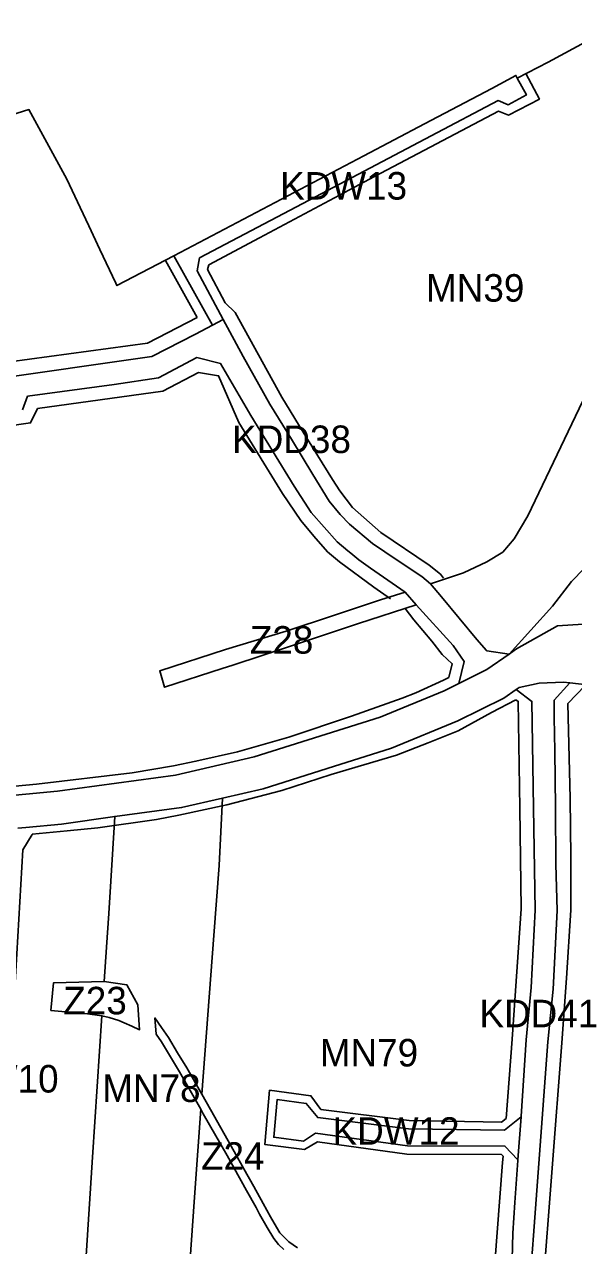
# Model space of a CAD drawing. Extents: x 7428841 to 7433518, y 5545054 to 5546840.
# Drawn here: x 7431956.4 to 7432155.6, y 5545406.8 to 5545850.4 of the extents above; entities that cross this region are included whole.
import ezdxf

# ---------------------------------------------------------------- set-up
doc = ezdxf.new("R2010")
doc.units = 0
for name, color, linetype in [('linie_rozgraniczajace', 7, 'Continuous'), ('linie_zabudowy_nieprzekraczalne', 7, 'Continuous'), ('oznaczenia_przeznaczen', 7, 'Continuous')]:
    doc.layers.add(name, color=color, linetype=linetype)

msp = doc.modelspace()

# ---------------------------------------------------------------- linework, layer by layer
at = {"layer": 'linie_rozgraniczajace'}
for points in [[(7432132.18, 5545621.69), (7432147.9, 5545639.12), (7432154.88, 5545648.03), (7432210.86, 5545705.54), (7432222.9, 5545721.64), (7432232.08, 5545736.14), (7432244.76, 5545759.7), (7432253.45, 5545777.62), (7432262.14, 5545795.55), (7432271.44, 5545817.17), (7432287.75, 5545858.73), (7432313.15, 5545921.27), (7432332.96, 5545968.95), (7432347.45, 5546006.55), (7432352.33, 5546020.89), (7432357.2, 5546035.24), (7432363.75, 5546056.3), (7432370.28, 5546073.1), (7432379.89, 5546097.52)], [(7432188.47, 5545859.56), (7432146.36, 5545836.73), (7432135.07, 5545830.88), (7432134.66, 5545831.89), (7432125.88, 5545827.16), (7432101.56, 5545814.32), (7432079.45, 5545802.66), (7432010.61, 5545766.29), (7431989.91, 5545755.55), (7431989.48, 5545756.43), (7431983.69, 5545768.63), (7431979.69, 5545777.2), (7431976.57, 5545783.86), (7431971.71, 5545794.23)], [(7432174.91, 5545747.04), (7432139.05, 5545671.94), (7432133.99, 5545663.57), (7432129.9, 5545658.64), (7432124.15, 5545655.2), (7432115.61, 5545651.14), (7432103.72, 5545647.14), (7432100.52, 5545649.81), (7432091.55, 5545655.81), (7432082.59, 5545661.8), (7432074.35, 5545668.92), (7432070.92, 5545672.36), (7432066.96, 5545677.25), (7432061.04, 5545686.93), (7432053.2, 5545699.7), (7432045.36, 5545712.47), (7432035.77, 5545729.82), (7432028.45, 5545743.22), (7432019.06, 5545760.95), (7432019.88, 5545765.56), (7432059.68, 5545786.57), (7432103.89, 5545809.9), (7432128.22, 5545822.74), (7432131.82, 5545821.25), (7432138.47, 5545824.77), (7432135.07, 5545830.88), (7432146.36, 5545836.73), (7432188.47, 5545859.56)], [(7432287.75, 5545858.73), (7432271.44, 5545817.17), (7432262.14, 5545795.55), (7432253.45, 5545777.62), (7432244.76, 5545759.7), (7432232.08, 5545736.14), (7432222.9, 5545721.64), (7432210.86, 5545705.54), (7432154.88, 5545648.03), (7432147.9, 5545639.12), (7432132.18, 5545621.69), (7432124.12, 5545622.82), (7432124.01, 5545622.95), (7432120.53, 5545626.94), (7432114.08, 5545634.7), (7432107.63, 5545642.46), (7432103.72, 5545647.14)], [(7432103.72, 5545647.14), (7432115.61, 5545651.14), (7432124.15, 5545655.2), (7432129.9, 5545658.64), (7432133.99, 5545663.57), (7432139.05, 5545671.94), (7432174.91, 5545747.04), (7432183.86, 5545765.9), (7432191.2, 5545780.73), (7432198.41, 5545796.09), (7432202.91, 5545805.04), (7432221.07, 5545842.2), (7432217.5, 5545843.79), (7432200.67, 5545852.98)], [(7432298.89, 5545854.26), (7432292.35, 5545837.77), (7432287.69, 5545826.02), (7432280.47, 5545808.59), (7432273.19, 5545791.34), (7432264.38, 5545773.09), (7432255.56, 5545754.84), (7432242.56, 5545730.56), (7432232.89, 5545715.25), (7432220.1, 5545698.07), (7432192.02, 5545669.12), (7432163.94, 5545640.18), (7432161, 5545636.55), (7432161.55, 5545631.78), (7432159.07, 5545632.52), (7432149.7, 5545631.91), (7432134.84, 5545623.57), (7432132.18, 5545621.69)], [(7431971.71, 5545794.23), (7431958.02, 5545819.48), (7431897.05, 5545800.35), (7431836.08, 5545781.23), (7431835.44, 5545785.08), (7431828.78, 5545823.75), (7431822.57, 5545843.63)], [(7431897.05, 5545800.35), (7431958.02, 5545819.48), (7431971.71, 5545794.23), (7431976.57, 5545783.86), (7431979.69, 5545777.2), (7431983.69, 5545768.63), (7431989.48, 5545756.43), (7431989.91, 5545755.55), (7432010.61, 5545766.29), (7432024.6, 5545741.15), (7432024.62, 5545741.12), (7432018.4, 5545737.92), (7432002.58, 5545729.76), (7431942.49, 5545721.23)], [(7431942.49, 5545721.23), (7432002.58, 5545729.76), (7432018.4, 5545737.92), (7432024.62, 5545741.12), (7432028.45, 5545743.22), (7432035.77, 5545729.82), (7432045.36, 5545712.47), (7432053.2, 5545699.7), (7432061.04, 5545686.93), (7432066.96, 5545677.25), (7432070.92, 5545672.36), (7432074.35, 5545668.92), (7432082.59, 5545661.8), (7432091.55, 5545655.81), (7432100.52, 5545649.81), (7432103.72, 5545647.14), (7432107.63, 5545642.46), (7432114.08, 5545634.7), (7432120.53, 5545626.94), (7432124.01, 5545622.95), (7432124.12, 5545622.82), (7432132.18, 5545621.69), (7432124.16, 5545616.01), (7432113.98, 5545610.97), (7432115.88, 5545618.94), (7432111.91, 5545624.76), (7432098.44, 5545639.51), (7432094.46, 5545644.16), (7432081.9, 5545652.94), (7432077.71, 5545655.86), (7432074.73, 5545658.29), (7432073.75, 5545659.16), (7432069.79, 5545662.45), (7432060.4, 5545673.09), (7432054.26, 5545682.68), (7432038.5, 5545708.36), (7432027.55, 5545727.17), (7432018.94, 5545729.39), (7432004.95, 5545721.98), (7431988.94, 5545719.56), (7431957.51, 5545715.35), (7431955.63, 5545710.38)], [(7431955.63, 5545710.38), (7431957.51, 5545715.35), (7431988.94, 5545719.56), (7432004.95, 5545721.98), (7432018.94, 5545729.39), (7432027.55, 5545727.17), (7432038.5, 5545708.36), (7432054.26, 5545682.68), (7432060.4, 5545673.09), (7432069.79, 5545662.45), (7432073.75, 5545659.16), (7432074.73, 5545658.29), (7432077.71, 5545655.86), (7432081.9, 5545652.94), (7432094.46, 5545644.16), (7432085.51, 5545641.36), (7432068.44, 5545635.66), (7432051.37, 5545629.96), (7432029.34, 5545623.36), (7432005.45, 5545615.58), (7432007.23, 5545609.6), (7432028.14, 5545616.39), (7432031.94, 5545617.63), (7432053.62, 5545624.84), (7432077.53, 5545632.81), (7432098.44, 5545639.51), (7432111.91, 5545624.76), (7432115.88, 5545618.94), (7432113.98, 5545610.97), (7432108.68, 5545608.34), (7432085.39, 5545598.8), (7432039.76, 5545584.32), (7432011.23, 5545577.7), (7431968.38, 5545571.86), (7431933.82, 5545568.58)], [(7431933.82, 5545568.58), (7431968.38, 5545571.86), (7432011.23, 5545577.7), (7432039.76, 5545584.32), (7432085.39, 5545598.8), (7432108.68, 5545608.34), (7432113.98, 5545610.97), (7432124.16, 5545616.01), (7432132.18, 5545621.69), (7432134.84, 5545623.57), (7432149.7, 5545631.91), (7432159.07, 5545632.52)], [(7432161.6, 5545610.32), (7432154.28, 5545611.17), (7432151.96, 5545611.44), (7432143.06, 5545611.08), (7432135.8, 5545609.55), (7432134.71, 5545608.78), (7432130.33, 5545605.68), (7432113.62, 5545597.4), (7432089.48, 5545587.51), (7432066.21, 5545580.13), (7432042.94, 5545572.74), (7432028.17, 5545569.31), (7432013.4, 5545565.89), (7431989.12, 5545562.68), (7431969.76, 5545559.94), (7431956.9, 5545558.72), (7431954.01, 5545558.44)], [(7432133.27, 5545401.81), (7432133.55, 5545411.29), (7432134.27, 5545422.46), (7432135.31, 5545437.71), (7432135.32, 5545437.91), (7432136.55, 5545453.6), (7432136.57, 5545453.8), (7432138.34, 5545481.5), (7432140.17, 5545500.5), (7432140.92, 5545514.58), (7432141.67, 5545528.66), (7432141.02, 5545565.76), (7432140.45, 5545604.48), (7432134.71, 5545608.78), (7432135.8, 5545609.55), (7432143.06, 5545611.08), (7432151.96, 5545611.44), (7432154.28, 5545611.17), (7432148.5, 5545604.9), (7432148.59, 5545598.65), (7432148.85, 5545586.48), (7432149.02, 5545565.9), (7432149.18, 5545545.32), (7432149.67, 5545528.57), (7432148.15, 5545499.91), (7432146.31, 5545480.82), (7432142.98, 5545436.66), (7432138.74, 5545379.48)], [(7432138.74, 5545379.48), (7432142.98, 5545436.66), (7432146.31, 5545480.82), (7432148.15, 5545499.91), (7432149.67, 5545528.57), (7432149.18, 5545545.32), (7432149.02, 5545565.9), (7432148.85, 5545586.48), (7432148.59, 5545598.65), (7432148.5, 5545604.9), (7432154.28, 5545611.17), (7432161.6, 5545610.32), (7432167.75, 5545607.49), (7432179.14, 5545595.76), (7432183.44, 5545589.39), (7432195.95, 5545574.36), (7432203.6, 5545569.04), (7432208.81, 5545561.69), (7432206.08, 5545525.88), (7432202.71, 5545474.72), (7432196.1, 5545386.25)], [(7432055.4, 5545405.97), (7432052.26, 5545408.11), (7432049.08, 5545411.44), (7432046.95, 5545414.9), (7432045.65, 5545417.28), (7432043, 5545422.13), (7432039.54, 5545428.26), (7432036.01, 5545434.62), (7432032.46, 5545441.01), (7432023.85, 5545456.18), (7432020.67, 5545461.77), (7432025.12, 5545519.43), (7432027.02, 5545544.82), (7432028.17, 5545569.31), (7432042.94, 5545572.74), (7432066.21, 5545580.13), (7432089.48, 5545587.51), (7432113.62, 5545597.4), (7432130.33, 5545605.68), (7432134.71, 5545608.78), (7432140.45, 5545604.48), (7432141.02, 5545565.76), (7432141.67, 5545528.66), (7432140.92, 5545514.58), (7432140.17, 5545500.5), (7432138.34, 5545481.5), (7432136.57, 5545453.8), (7432136.55, 5545453.6), (7432130.5, 5545448.66), (7432095.68, 5545449.23), (7432062.77, 5545453.3), (7432058.63, 5545458.42), (7432048.04, 5545459.81), (7432046.84, 5545446.12), (7432057.64, 5545444.75), (7432062, 5545447.65), (7432095.3, 5545443.05), (7432130.71, 5545442.91), (7432135.32, 5545437.91), (7432135.31, 5545437.71), (7432134.27, 5545422.46), (7432133.55, 5545411.29), (7432133.27, 5545401.81)], [(7431976.25, 5545363.59), (7431981.09, 5545438.88), (7431984.46, 5545490.31), (7431987.14, 5545489.68), (7431990.64, 5545488.55), (7431992.52, 5545487.74), (7431995.33, 5545486.47), (7431998.12, 5545485.21), (7431997.48, 5545494.21), (7431993.53, 5545501.47), (7431985.24, 5545502.71), (7431986.16, 5545515.18), (7431986.99, 5545527.39), (7431989.12, 5545562.68), (7432013.4, 5545565.89), (7432028.17, 5545569.31), (7432027.02, 5545544.82), (7432025.12, 5545519.43), (7432020.67, 5545461.77), (7432015.23, 5545471.35), (7432011.94, 5545476.86), (7432008.61, 5545482.43), (7432006.11, 5545485.97), (7432003.73, 5545489.47), (7432004.13, 5545483.62), (7432006.07, 5545480.84), (7432012.6, 5545469.89), (7432020.32, 5545456.32), (7432018.14, 5545426.1), (7432016.2, 5545398.51)], [(7431954.01, 5545558.44), (7431956.9, 5545558.72), (7431969.76, 5545559.94), (7431989.12, 5545562.68), (7431986.99, 5545527.39), (7431986.16, 5545515.18), (7431985.24, 5545502.71), (7431966.86, 5545502.19), (7431965.95, 5545492.23), (7431972.63, 5545491.63), (7431979.3, 5545491.02), (7431984.45, 5545490.31), (7431984.46, 5545490.31), (7431981.09, 5545438.88), (7431976.25, 5545363.59), (7431916.07, 5545367.52)], [(7432050.46, 5545405.31), (7432048.59, 5545407.18), (7432046.8, 5545409.37), (7432044.37, 5545413.36), (7432041.7, 5545418.25), (7432040.39, 5545420.65), (7432036.93, 5545426.78), (7432029.86, 5545439.52), (7432021.24, 5545454.7), (7432020.32, 5545456.32), (7432012.6, 5545469.89), (7432006.07, 5545480.84), (7432004.13, 5545483.62), (7432003.73, 5545489.47), (7432006.11, 5545485.97), (7432008.61, 5545482.43), (7432011.94, 5545476.86), (7432015.23, 5545471.35), (7432020.67, 5545461.77), (7432023.85, 5545456.18), (7432032.46, 5545441.01), (7432036.01, 5545434.62), (7432039.54, 5545428.26), (7432043, 5545422.13), (7432045.65, 5545417.28), (7432046.95, 5545414.9), (7432049.08, 5545411.44), (7432052.26, 5545408.11), (7432055.4, 5545405.97)], [(7432016.2, 5545398.51), (7432018.14, 5545426.1), (7432020.32, 5545456.32), (7432021.24, 5545454.7), (7432029.86, 5545439.52), (7432036.93, 5545426.78), (7432040.39, 5545420.65), (7432041.7, 5545418.25), (7432044.37, 5545413.36), (7432046.8, 5545409.37), (7432048.59, 5545407.18), (7432050.46, 5545405.31)]]:
    msp.add_lwpolyline(points, dxfattribs=at)
for points in [[(7432010.61, 5545766.29), (7432079.45, 5545802.66), (7432101.56, 5545814.32), (7432125.88, 5545827.16), (7432134.66, 5545831.89), (7432135.07, 5545830.88), (7432138.47, 5545824.77), (7432131.82, 5545821.25), (7432128.22, 5545822.74), (7432103.89, 5545809.9), (7432059.68, 5545786.57), (7432019.88, 5545765.56), (7432019.06, 5545760.95), (7432028.45, 5545743.22), (7432024.62, 5545741.12), (7432024.6, 5545741.15)], [(7432005.45, 5545615.58), (7432029.34, 5545623.36), (7432051.37, 5545629.96), (7432068.44, 5545635.66), (7432085.51, 5545641.36), (7432094.46, 5545644.16), (7432098.44, 5545639.51), (7432077.53, 5545632.81), (7432053.62, 5545624.84), (7432031.94, 5545617.63), (7432028.14, 5545616.39), (7432007.23, 5545609.6)], [(7431965.95, 5545492.23), (7431966.86, 5545502.19), (7431985.24, 5545502.71), (7431993.53, 5545501.47), (7431997.48, 5545494.21), (7431998.12, 5545485.21), (7431995.33, 5545486.47), (7431992.52, 5545487.74), (7431990.64, 5545488.55), (7431987.14, 5545489.68), (7431984.46, 5545490.31), (7431984.45, 5545490.31), (7431979.3, 5545491.02), (7431972.63, 5545491.63)], [(7432046.84, 5545446.12), (7432048.04, 5545459.81), (7432058.63, 5545458.42), (7432062.77, 5545453.3), (7432095.68, 5545449.23), (7432130.5, 5545448.66), (7432136.55, 5545453.6), (7432135.32, 5545437.91), (7432130.71, 5545442.91), (7432095.3, 5545443.05), (7432062, 5545447.65), (7432057.64, 5545444.75)]]:
    msp.add_lwpolyline(points, close=True, dxfattribs=at)
at = {"layer": 'linie_zabudowy_nieprzekraczalne'}
for points in [[(7432138.26, 5545832.59), (7432143.22, 5545823.31), (7432132, 5545817.39), (7432128.4, 5545818.88), (7432083.42, 5545795.14), (7432041.67, 5545772.91), (7432023.31, 5545763.03), (7432022.82, 5545761.34), (7432029.17, 5545749.29)], [(7432019.04, 5545743.9), (7432007.56, 5545764.59)], [(7432029.17, 5545749.29), (7432032.79, 5545745.7), (7432049.69, 5545714.98), (7432057.46, 5545702.33), (7432068.15, 5545685.09), (7432070.81, 5545680.94), (7432075.33, 5545674.97), (7432085.63, 5545665.78), (7432103.16, 5545653.95), (7432107.27, 5545650.69), (7432108.45, 5545649.27)], [(7431936.68, 5545725.89), (7432001.04, 5545734.59), (7432019.04, 5545743.9)], [(7431961.11, 5545710.93), (7431958.6, 5545705.65), (7431940.1, 5545703), (7431936.68, 5545725.89)], [(7432089.12, 5545641.8), (7432083.16, 5545645.96), (7432070.66, 5545655.22), (7432066.3, 5545658.85), (7432061.3, 5545664.52), (7432056.6, 5545670.19), (7432050.05, 5545679.99), (7432034.21, 5545705.8), (7432026.82, 5545722.78), (7432019.46, 5545724.01), (7432006.52, 5545717.16), (7431961.11, 5545710.93)], [(7432110.31, 5545613.14), (7432111.58, 5545618.15), (7432107.94, 5545621.51), (7432104.14, 5545626.33), (7432097.65, 5545634.14), (7432094.44, 5545638.25)], [(7431748.06, 5545609.87), (7431758.17, 5545603.9), (7431772.63, 5545595.72), (7431780.9, 5545591.16), (7431788.24, 5545587.54), (7431793.62, 5545585.27), (7431814.53, 5545578.23), (7431839.6, 5545570.04), (7431851.69, 5545567.23), (7431866.48, 5545565.87), (7431883.65, 5545567.05), (7431938.69, 5545572.35), (7431960.73, 5545574.4), (7431995.49, 5545578.54), (7432010.41, 5545581.02), (7432018.56, 5545582.74), (7432033.67, 5545586.14), (7432052.34, 5545591.47), (7432075.03, 5545599.16), (7432093.38, 5545605.62), (7432098.37, 5545607.65), (7432108.45, 5545612.2), (7432110.31, 5545613.14)], [(7432199.08, 5545569.34), (7432194.45, 5545572.64), (7432189.54, 5545577.26), (7432183.25, 5545584.92), (7432178.01, 5545592.04), (7432176.32, 5545594.45), (7432167.31, 5545607.42), (7432161.6, 5545610.32), (7432159.81, 5545610.31), (7432153.54, 5545603.66)], [(7432134.66, 5545605.06), (7432125.8, 5545600.4), (7432113.77, 5545593.8), (7432102.86, 5545589.41), (7432091.31, 5545584.94), (7432067.66, 5545577.87), (7432049.77, 5545572.14), (7432029.82, 5545566.86), (7432012.34, 5545563.21), (7432004.33, 5545561.61), (7431982.98, 5545558.55), (7431971.92, 5545557.43), (7431959.18, 5545556.19)], [(7432131.1, 5545452.93), (7432133.29, 5545481.83), (7432136.59, 5545529.1), (7432136.13, 5545565.66), (7432135.5, 5545604.49), (7432134.66, 5545605.06)], [(7432153.54, 5545603.66), (7432154.37, 5545569.23), (7432154.56, 5545548.02), (7432154.6, 5545528.65), (7432153.03, 5545503.9), (7432151.29, 5545480.41), (7432144.29, 5545389.36), (7432143.72, 5545383.25), (7432143.33, 5545378.72)], [(7431959.13, 5545556.14), (7431955.84, 5545550.5), (7431952.13, 5545487.57), (7431952.72, 5545480.8), (7431947.87, 5545409.16), (7431950.28, 5545406.46), (7431948.64, 5545387.4), (7431925.91, 5545389.23), (7431927.43, 5545408.27), (7431930, 5545410.43), (7431935.05, 5545482.62), (7431936.47, 5545524.63), (7431938.22, 5545549.97), (7431934.91, 5545553.91)], [(7432130.03, 5545439.28), (7432129.4, 5545439.91), (7432095.09, 5545440.05), (7432062.64, 5545444.53), (7432057.98, 5545441.69), (7432043.6, 5545443.51), (7432045.33, 5545463.2), (7432060.32, 5545461.23), (7432063.91, 5545456.19), (7432095.89, 5545452.22), (7432129.45, 5545451.68), (7432131.1, 5545452.93)], [(7432124.52, 5545367.61), (7432125.47, 5545379.64), (7432126.39, 5545392.38), (7432127.84, 5545411.5), (7432129.84, 5545436.97), (7432130.03, 5545439.28)]]:
    msp.add_lwpolyline(points, dxfattribs=at)

# ---------------------------------------------------------------- texts
at = {"layer": 'oznaczenia_przeznaczen'}
for s, p in [('KDW13', (7432049.13, 5545786.78)), ('MN39', (7432102.07, 5545749.69)), ('KDD38', (7432031.72, 5545694.7)), ('Z28', (7432038.13, 5545621.83)), ('Z23', (7431970.46, 5545490.79)), ('KDD41', (7432121.45, 5545486.1)), ('MN79', (7432063.53, 5545471.86)), ('KDW10', (7431922.7, 5545462.39)), ('MN78', (7431984.58, 5545458.96)), ('KDW12', (7432068.15, 5545443.41)), ('Z24', (7432020.43, 5545434.33))]:
    msp.add_text(s, height=10, dxfattribs=at).set_placement(p)

doc.saveas('drawing.dxf')
